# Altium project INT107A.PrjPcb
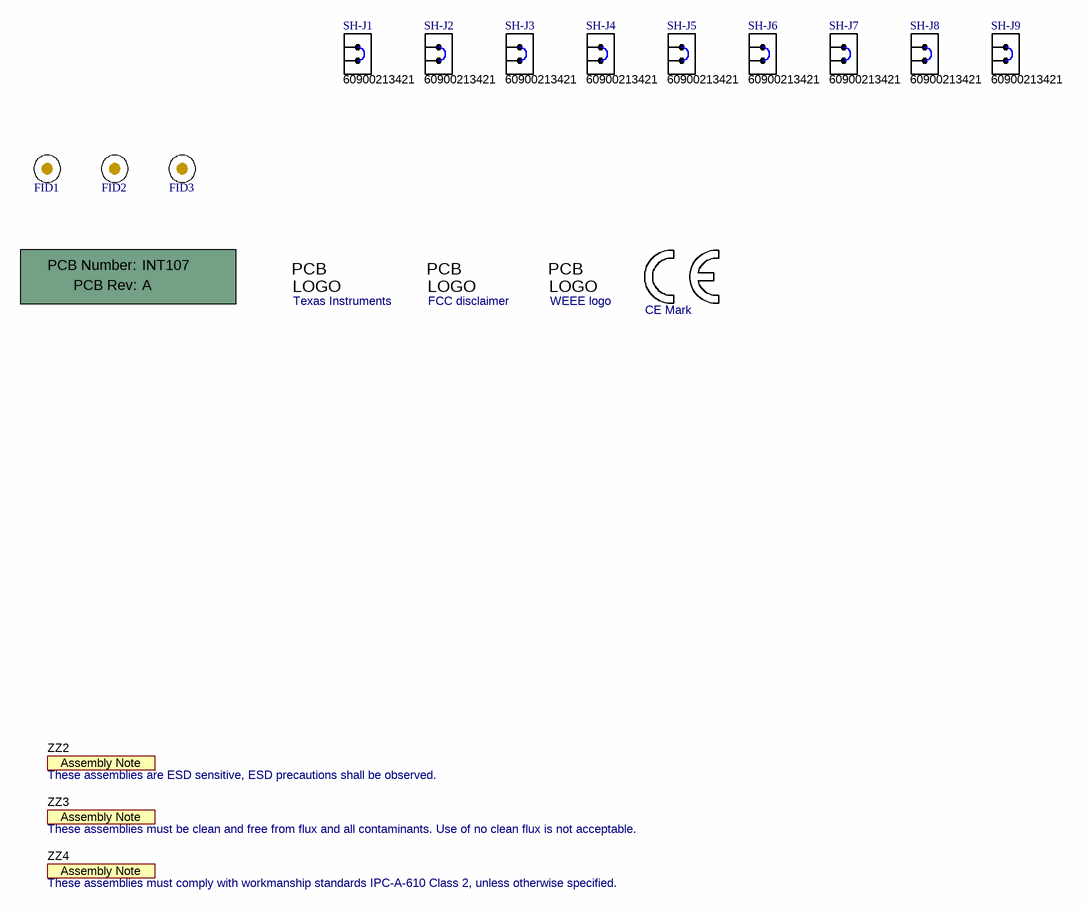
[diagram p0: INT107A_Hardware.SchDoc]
CopyrightYear: 2019; EVM_Orderable: BOOSTXL-CANFD-LIN; Orderable: BOOSTXL-CANFD-LIN; PCB_Layout: Jonathan Nerger; PCB_Rev: A; PRJ_Customer: Public Release; PRJ_Engineer: Jonathan Nerger; PRJ_Number: INT107; PRJ_Title: SPI to CAN FD SBC + LIN BoosterPack; SCH_Rev: A; TechSupport: http://www.ti.com/support; TID: N/A
2 sheets, 161 parts. Net scope: global (net labels, ports and power ports of the same name join across sheets).
Board file: INT107A_PCB.PcbDoc
Sheets:
  INT107A_Hardware.SchDoc
  INT107A_Schematic.SchDoc

## Sheet INT107A_Hardware.SchDoc: BOOSTXL-CANFD-LIN Hardwdare
size 431 x 279 mm; Date: Not shown in title block; ApprovedBy: Not shown in title block; CheckedBy: Not shown in title block; Author: Not shown in title block; CompanyName: Texas Instruments; DrawnBy: Jonathan Nerger; Engineer: Jonathan Nerger; Organization: Texas Instruments; Address1: Not shown in title block; Address2: Not shown in title block; Address3: Not shown in title block; Address4: Not shown in title block; DocumentNumber: 2; Revision: Use project parameter SCH_Rev; SheetNumber: 2; SheetTotal: 2; PageSetup: Record=PageOptions¦CenterHorizontal=True¦CenterVertical=True¦PrintScale=1.00¦XCorrection=1.00¦YCorrection=1.00¦PrintKind=0¦BorderSize=5000000¦LeftOffset=0¦BottomOffset=0¦Orientation=2¦PaperLength=1000¦PaperWidth=1000¦Scale=100¦PaperSource=15¦PrintQuality=600¦MediaType=1¦DitherType=10¦PaperKind=Letter¦PrintScaleMode=1

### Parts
!PCB1  Printed Circuit Board  (value not drawn)  (mechanical)
FID1  Fiducial  [Fiducial10-20]  (value not drawn)
FID2  Fiducial  [Fiducial10-20]  (value not drawn)
FID3  Fiducial  [Fiducial10-20]  (value not drawn)
Logo1  Texas Instruments  [TI_Stacked_Overlay_Small]  (no BOM)
Logo3  FCC disclaimer  [FCC_disclaimer]  (no BOM)
LOGO4  CE Mark  [CE_Mark_5mm]  (no BOM)
Logo5  WEEE logo  [WEEE_Minimum]  (no BOM)
SH-J1  60900213421  [Wurth_60900213421]
SH-J2  60900213421  [Wurth_60900213421]
SH-J3  60900213421  [Wurth_60900213421]
SH-J4  60900213421  [Wurth_60900213421]
SH-J5  60900213421  [Wurth_60900213421]
SH-J6  60900213421  [Wurth_60900213421]
SH-J7  60900213421  [Wurth_60900213421]
SH-J8  60900213421  [Wurth_60900213421]
SH-J9  60900213421  [Wurth_60900213421]
ZZ2  These assemblies are ESD sensitive, ESD precautions shall be observed.  [AssemblyNote]  (no BOM)
ZZ3  These assemblies must be clean and free from flux and all contaminants. Use of no clean flux is not acceptable.  [AssemblyNote]  (no BOM)
ZZ4  These assemblies must comply with workmanship standards IPC-A-610 Class 2, unless otherwise specified.  [AssemblyNote]  (no BOM)

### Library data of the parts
!PCB1 = CMP-0003618-2: Manufacturer: Any; PartNumber: INT107
FID1-FID3 = CMP-0077181-1: Fiducial mark.  There is nothing to buy or mount.
Logo1 = CMP-0074838-1: Texas Instrument Corporate Signature; SymbolCreator: a0412235; Lib Reference: TI_Logo
Logo3 = CMP-0074847-1: FCC_disclaimer
LOGO4 = CMP-0074844-1: SymbolCreator: a0412235
Logo5 = CMP-0074769-1
SH-J1-SH-J9 = CMP-0003761-2: Shunt, 2.54mm, Gold, Black; Manufacturer: Wurth Elektronik
ZZ2 = CMP-0077236-1
ZZ3 = CMP-0077237-1
ZZ4 = CMP-0077238-1

## Sheet INT107A_Schematic.SchDoc: BOOSTXL-CANFD-LIN Schematic
size 431 x 279 mm; Date: Not shown in title block; ApprovedBy: Not shown in title block; CheckedBy: Not shown in title block; Author: Not shown in title block; CompanyName: Texas Instruments; DrawnBy: Jonathan Nerger; Engineer: Jonathan Nerger; Organization: Texas Instruments; Address1: Not shown in title block; Address2: Not shown in title block; Address3: Not shown in title block; Address4: Not shown in title block; DocumentNumber: 1; Revision: Use project parameter SCH_Rev; SheetNumber: 1; SheetTotal: 2; PageSetup: Record=PageOptions¦CenterHorizontal=True¦CenterVertical=True¦PrintScale=1.00¦XCorrection=1.00¦YCorrection=1.00¦PrintKind=0¦BorderSize=5000000¦LeftOffset=0¦BottomOffset=0¦Orientation=2¦PaperLength=1000¦PaperWidth=1000¦Scale=100¦PaperSource=15¦PrintQuality=600¦MediaType=1¦DitherType=10¦PaperKind=Letter¦PrintScaleMode=1
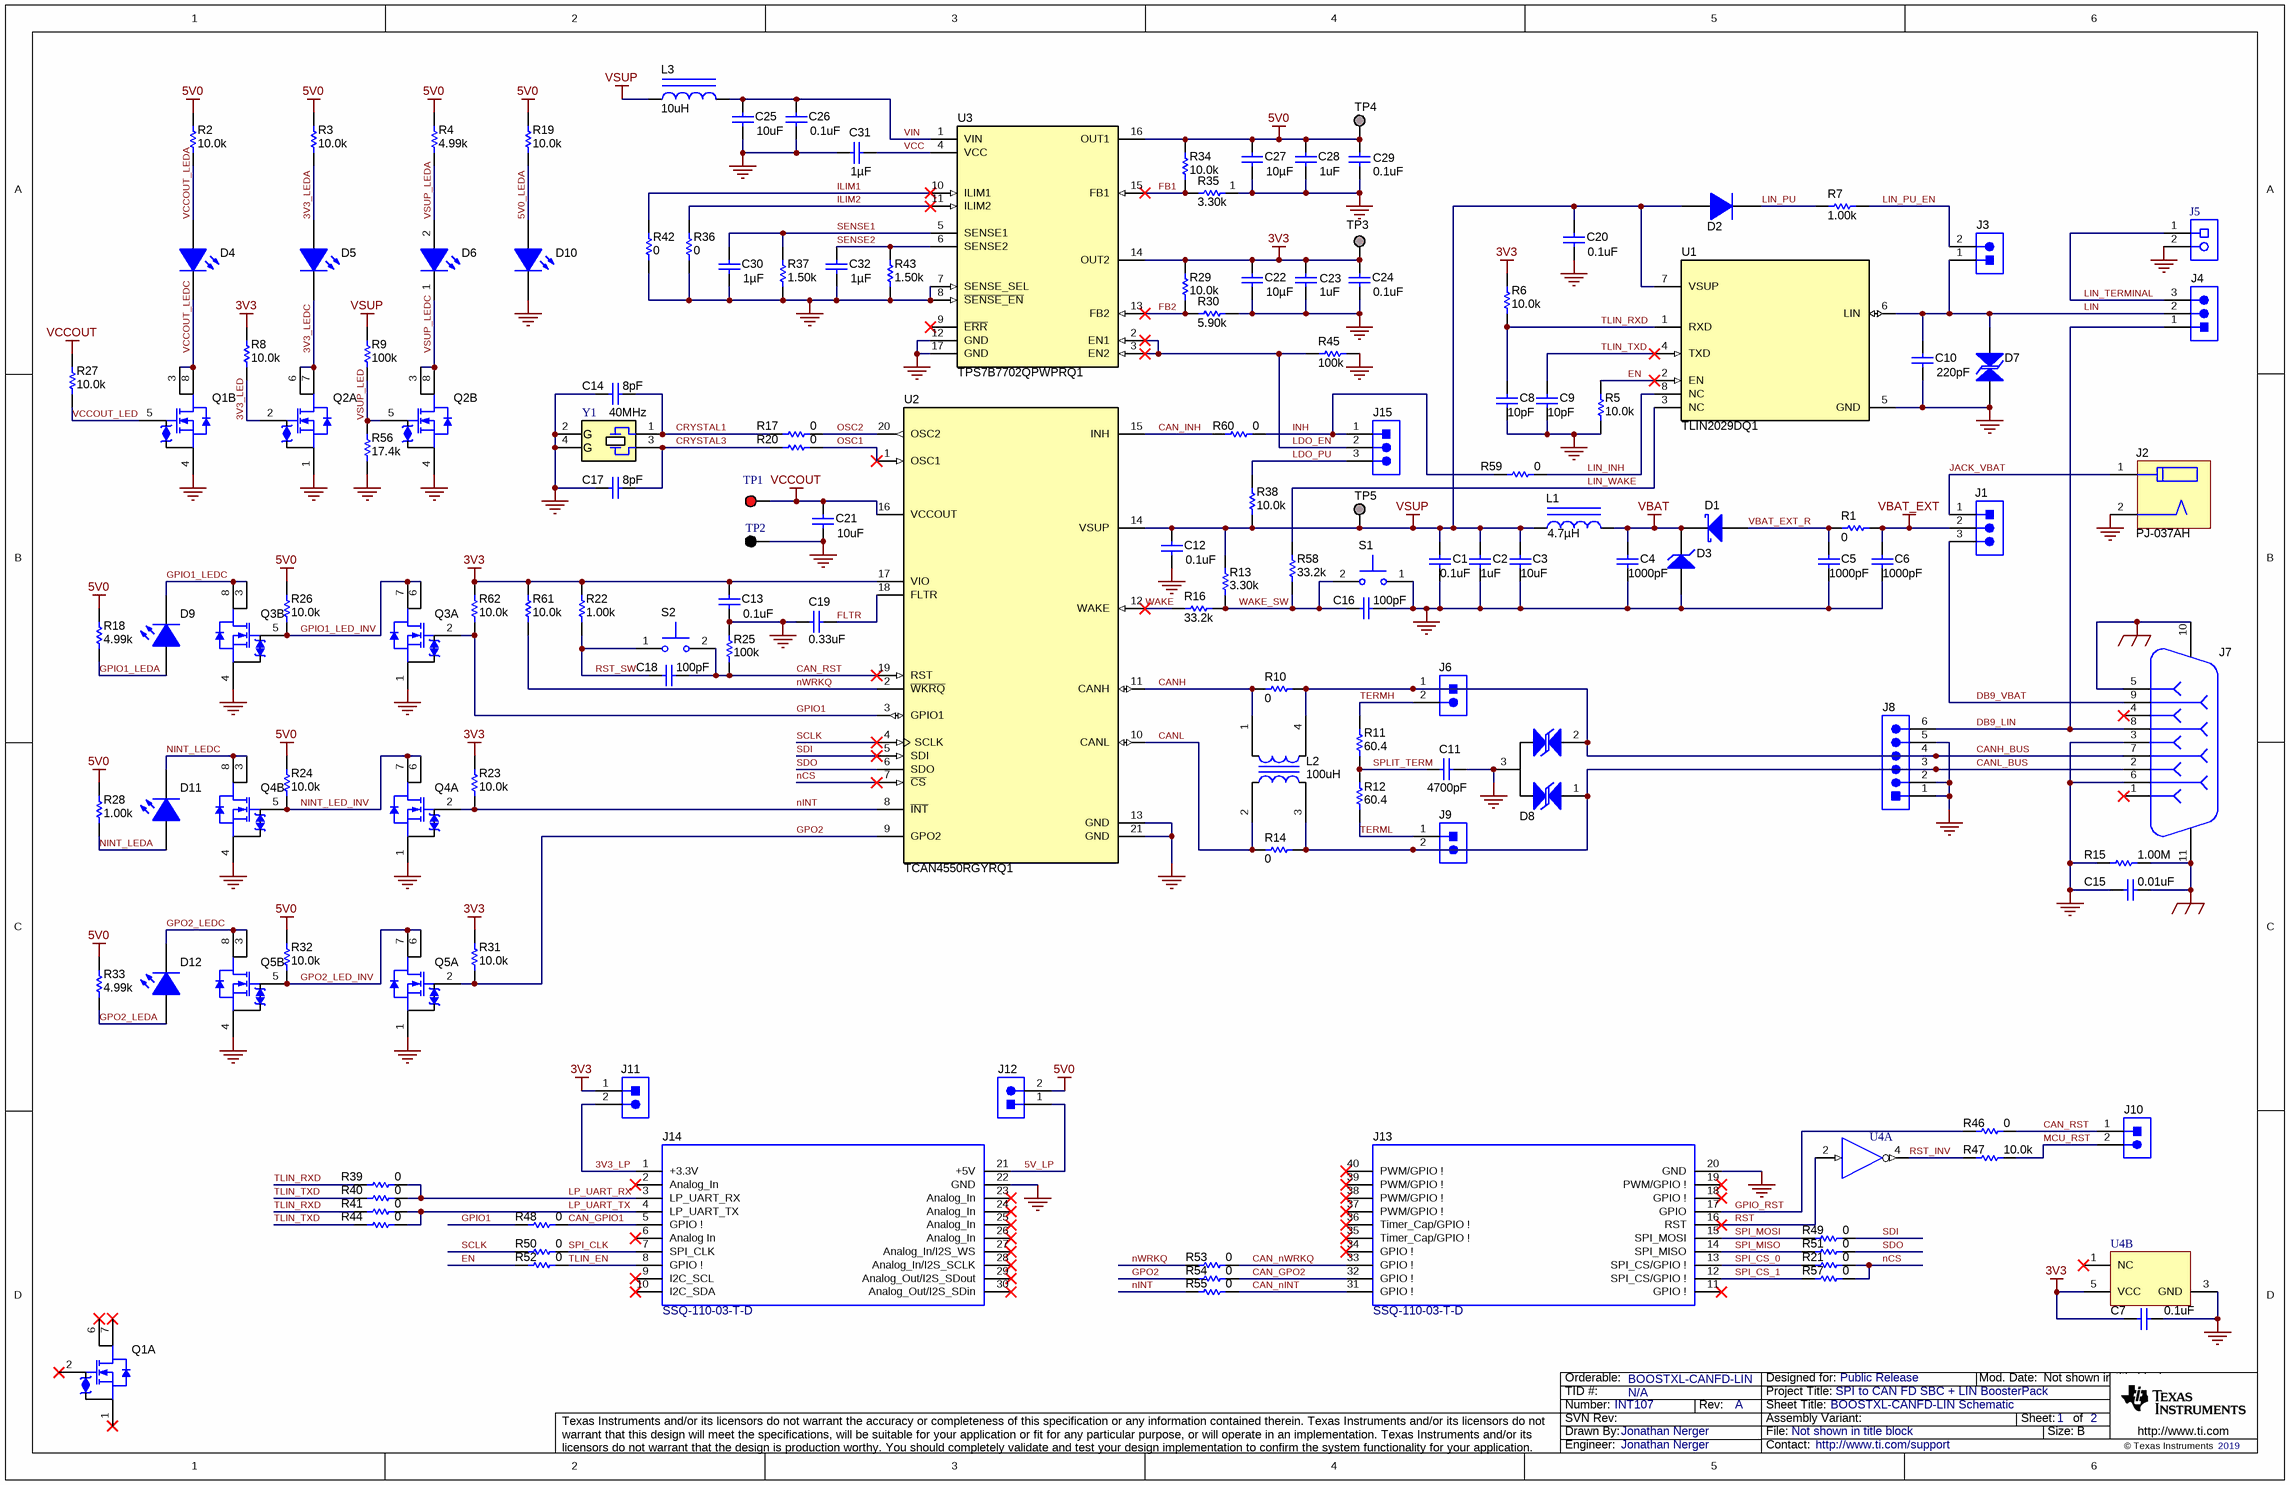
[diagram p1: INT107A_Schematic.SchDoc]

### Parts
C1  ValueDisplayed: 0.1uF  [0603S]  (hidden comment: CGA3E2X7R1H104K080AA)
C2  ValueDisplayed: 1uF  [0603S]  (hidden comment: UMK107AB7105KA-T)
C3  ValueDisplayed: 10uF  [1206_180]  (hidden comment: CL31B106KBHNNNE)
C4  ValueDisplayed: 1000pF  [0603S]  (hidden comment: CGA3E2X7R2A102K080AA)
C5  ValueDisplayed: 1000pF  [0603S]  (hidden comment: CGA3E2X7R2A102K080AA)
C6  ValueDisplayed: 1000pF  [0603S]  (hidden comment: CGA3E2X7R2A102K080AA)
C7  ValueDisplayed: 0.1uF  [0603S]  (hidden comment: CGA3E2X7R1H104K080AA)
C8  ValueDisplayed: 10pF  [0603S]  (hidden comment: CGA3E2NP01H100D080AA)
C9  ValueDisplayed: 10pF  [0603S]  (hidden comment: CGA3E2NP01H100D080AA)
C10  ValueDisplayed: 220pF  [0603S]  (hidden comment: 06035A221FAT2A)
C11  ValueDisplayed: 4700pF  [0603]  (hidden comment: 06031C472KAT2A)
C12  ValueDisplayed: 0.1uF  [0603S]  (hidden comment: CGA3E2X7R1H104K080AA)
C13  ValueDisplayed: 0.1uF  [0603S]  (hidden comment: CGA3E2X7R1H104K080AA)
C14  ValueDisplayed: 8pF  [0402S]  (hidden comment: CC0402DRNPO9BN8R0)
C15  ValueDisplayed: 0.01uF  [1206]  (hidden comment: 12061C103JAT2A)
C16  ValueDisplayed: 100pF  [0603S]  (hidden comment: 06035A101JAT2A)
C17  ValueDisplayed: 8pF  [0402S]  (hidden comment: CC0402DRNPO9BN8R0)
C18  ValueDisplayed: 100pF  [0603S]  (hidden comment: 06035A101JAT2A)
C19  ValueDisplayed: 0.33uF  [0603S]  (hidden comment: C0603C334K4RACTU)
C20  ValueDisplayed: 0.1uF  [0603S]  (hidden comment: CGA3E2X7R1H104K080AA)
C21  ValueDisplayed: 10uF  [0805]  (hidden comment: CL21B106KOQNNNE)
C22  ValueDisplayed: 10µF  [1206_180]  (hidden comment: C1206C106K4RACTU)
C23  ValueDisplayed: 1uF  [0603S]  (hidden comment: UMK107AB7105KA-T)
C24  ValueDisplayed: 0.1uF  [0603S]  (hidden comment: CGA3E2X7R1H104K080AA)
C25  ValueDisplayed: 10uF  [1206_180]  (hidden comment: CL31B106KBHNNNE)
C26  ValueDisplayed: 0.1uF  [0603S]  (hidden comment: CGA3E2X7R1H104K080AA)
C27  ValueDisplayed: 10µF  [1206_180]  (hidden comment: C1206C106K4RACTU)
C28  ValueDisplayed: 1uF  [0603S]  (hidden comment: UMK107AB7105KA-T)
C29  ValueDisplayed: 0.1uF  [0603S]  (hidden comment: CGA3E2X7R1H104K080AA)
C30  ValueDisplayed: 1µF  [0603S]  (hidden comment: GCM188R71C105KA64J)
C31  ValueDisplayed: 1µF  [0603S]  (hidden comment: GCM188R71C105KA64J)
C32  ValueDisplayed: 1µF  [0603S]  (hidden comment: GCM188R71C105KA64J)
D1  MBRA140T3G  [SMA]  (value not drawn)
D2  1N4148W-TP  [SOD-123]  (value not drawn)
D3  3SMAJ5936B-TP  [SMA]  (value not drawn)
D4  150060GS75000  [WL-SMCW_GREEN]  (value not drawn)
D5  150060GS75000  [WL-SMCW_GREEN]  (value not drawn)
D6  150060GS75000  [WL-SMCW_GREEN]  (value not drawn)
D7  PESD1LIN,115  [SOD-323-Bi]  (value not drawn)
D8  PESD1CAN,215  [SOT-23]  (value not drawn)
D9  150060YS75000  [WL-SMCW_YELLOW]  (value not drawn)
D10  150060GS75000  [WL-SMCW_GREEN]  (value not drawn)
D11  150060BS75000  [WL-SMCW_Blue]  (value not drawn)
D12  150060RS75000  [WL-SMCW_RED]  (value not drawn)
J1  TSW-103-07-G-S  [TSW-103-07-G-S]  (value not drawn)
J2  PJ-037AH  [CUI_PJ-037AH]
J3  TSW-102-07-G-S  [TSW-102-07-G-S]  (value not drawn)
J4  TSW-103-07-G-S  [TSW-103-07-G-S]  (value not drawn)
J5  OSTVN02A150  [On-Shore_OSTVN02A150]  (value not drawn)
J6  TSW-102-07-G-S  [TSW-102-07-G-S]  (value not drawn)
J7  5747840-5  [TE_5747840-5]  (value not drawn)
J8  TSW-106-07-G-S  [TSW-106-07-G-S]  (value not drawn)
J9  TSW-102-07-G-S  [TSW-102-07-G-S]  (value not drawn)
J10  TSW-102-07-G-S  [TSW-102-07-G-S]  (value not drawn)
J11  TSW-102-07-G-S  [TSW-102-07-G-S]  (value not drawn)
J12  TSW-102-07-G-S  [TSW-102-07-G-S]  (value not drawn)
J13  SSQ-110-03-T-D  [BoosterPack_40pin_J2J4]
J14  SSQ-110-03-T-D  [BoosterPack_40pin_J1J3]
J15  TSW-103-07-G-S  [TSW-103-07-G-S]  (value not drawn)
L1  ValueDisplayed: 4.7µH  [B82462A4]  (hidden comment: B82462A4472M000)
L2  ValueDisplayed: 100uH  [ACT45B]  (hidden comment: ACT45B-101-2P-TL003)
L3  ValueDisplayed: 10uH  [WE-TPC_2828]  (hidden comment: 744025100)
Q1  CSD85301Q2  [DQK0006B]  (value not drawn)  (parts A,B of 2)
Q2  CSD85301Q2  [DQK0006B]  (value not drawn)  (parts A,B of 2)
Q3  CSD85301Q2  [DQK0006B]  (value not drawn)  (parts A,B of 2)
Q4  CSD85301Q2  [DQK0006B]  (value not drawn)  (parts A,B of 2)
Q5  CSD85301Q2  [DQK0006B]  (value not drawn)  (parts A,B of 2)
R1  ValueDisplayed: 0  [5106]  (hidden comment: 5106)
R2  ValueDisplayed: 10.0k  [0402S]  (hidden comment: RC0402FR-0710KL)
R3  ValueDisplayed: 10.0k  [0402S]  (hidden comment: RC0402FR-0710KL)
R4  ValueDisplayed: 4.99k  [0402S]  (hidden comment: RC0402FR-074K99L)
R5  ValueDisplayed: 10.0k  [0402S]  (hidden comment: RC0402FR-0710KL)
R6  ValueDisplayed: 10.0k  [0402S]  (hidden comment: RC0402FR-0710KL)
R7  ValueDisplayed: 1.00k  [0402S]  (hidden comment: CRCW04021K00FKED)
R8  ValueDisplayed: 10.0k  [0402S]  (hidden comment: RC0402FR-0710KL)
R9  ValueDisplayed: 100k  [0402S]  (hidden comment: RC1005F104CS)
R10  ValueDisplayed: 0  [1206]  (hidden comment: ERJ-8GEY0R00V)
R11  ValueDisplayed: 60.4  [0603]  (hidden comment: RC0603FR-0760R4L)
R12  ValueDisplayed: 60.4  [0603]  (hidden comment: RC0603FR-0760R4L)
R13  ValueDisplayed: 3.30k  [0402S]  (hidden comment: ERJ-2RKF3301X)
R14  ValueDisplayed: 0  [1206]  (hidden comment: ERJ-8GEY0R00V)
R15  ValueDisplayed: 1.00M  [0402S]  (hidden comment: ERJ-2RKF1004X)
R16  ValueDisplayed: 33.2k  [0402S]  (hidden comment: CRCW040233K2FKED)
R17  ValueDisplayed: 0  [0402S]  (hidden comment: RC0402JR-070RL)
R18  ValueDisplayed: 4.99k  [0402S]  (hidden comment: RC0402FR-074K99L)
R19  ValueDisplayed: 10.0k  [0402S]  (hidden comment: RC0402FR-0710KL)
R20  ValueDisplayed: 0  [0402S]  (hidden comment: RC0402JR-070RL)
R21  ValueDisplayed: 0  [0402S]  (hidden comment: RC0402JR-070RL)
R22  ValueDisplayed: 1.00k  [0402S]  (hidden comment: RC0402FR-071KL)
R23  ValueDisplayed: 10.0k  [0402S]  (hidden comment: RC0402FR-0710KL)
R24  ValueDisplayed: 10.0k  [0402S]  (hidden comment: RC0402FR-0710KL)
R25  ValueDisplayed: 100k  [0402S]  (hidden comment: RC1005F104CS)
R26  ValueDisplayed: 10.0k  [0402S]  (hidden comment: RC0402FR-0710KL)
R27  ValueDisplayed: 10.0k  [0402S]  (hidden comment: RC0402FR-0710KL)
R28  ValueDisplayed: 1.00k  [0402S]  (hidden comment: RC0402FR-071KL)
R29  ValueDisplayed: 10.0k  [0402S]  (hidden comment: RC0402FR-0710KL)
R30  ValueDisplayed: 5.90k  [0402S]  (hidden comment: CRCW04025K90FKED)
R31  ValueDisplayed: 10.0k  [0402S]  (hidden comment: RC0402FR-0710KL)
R32  ValueDisplayed: 10.0k  [0402S]  (hidden comment: RC0402FR-0710KL)
R33  ValueDisplayed: 4.99k  [0402S]  (hidden comment: RC0402FR-074K99L)
R34  ValueDisplayed: 10.0k  [0402S]  (hidden comment: RC0402FR-0710KL)
R35  ValueDisplayed: 3.30k  [0402S]  (hidden comment: ERJ-2RKF3301X)
R36  ValueDisplayed: 0  [0402S]  (hidden comment: RC0402JR-070RL)
R37  ValueDisplayed: 1.50k  [0402S]  (hidden comment: CRCW04021K50FKED)
R38  ValueDisplayed: 10.0k  [0402S]  (hidden comment: RC0402FR-0710KL)
R39  ValueDisplayed: 0  [0402S]  (hidden comment: RC0402JR-070RL)
R40  ValueDisplayed: 0  [0402S]  (hidden comment: RC0402JR-070RL)
R41  ValueDisplayed: 0  [0402S]  (hidden comment: RC0402JR-070RL)
R42  ValueDisplayed: 0  [0402S]  (hidden comment: RC0402JR-070RL)
R43  ValueDisplayed: 1.50k  [0402S]  (hidden comment: CRCW04021K50FKED)
R44  ValueDisplayed: 0  [0402S]  (hidden comment: RC0402JR-070RL)
R45  ValueDisplayed: 100k  [0402S]  (hidden comment: RC1005F104CS)
R46  ValueDisplayed: 0  [0402S]  (hidden comment: RC0402JR-070RL)
R47  ValueDisplayed: 10.0k  [0402S]  (hidden comment: RC0402FR-0710KL)
R48  ValueDisplayed: 0  [0402S]  (hidden comment: RC0402JR-070RL)
R49  ValueDisplayed: 0  [0402S]  (hidden comment: RC0402JR-070RL)
R50  ValueDisplayed: 0  [0402S]  (hidden comment: RC0402JR-070RL)
R51  ValueDisplayed: 0  [0402S]  (hidden comment: RC0402JR-070RL)
R52  ValueDisplayed: 0  [0402S]  (hidden comment: RC0402JR-070RL)
R53  ValueDisplayed: 0  [0402S]  (hidden comment: RC0402JR-070RL)
R54  ValueDisplayed: 0  [0402S]  (hidden comment: RC0402JR-070RL)
R55  ValueDisplayed: 0  [0402S]  (hidden comment: RC0402JR-070RL)
R56  ValueDisplayed: 17.4k  [0402S]  (hidden comment: CRCW040217K4FKED)
R57  ValueDisplayed: 0  [0402S]  (hidden comment: RC0402JR-070RL)
R58  ValueDisplayed: 33.2k  [0402S]  (hidden comment: CRCW040233K2FKED)
R59  ValueDisplayed: 0  [0402S]  (hidden comment: RC0402JR-070RL)
R60  ValueDisplayed: 0  [0402S]  (hidden comment: RC0402JR-070RL)
R61  ValueDisplayed: 10.0k  [0402S]  (hidden comment: RC0402FR-0710KL)
R62  ValueDisplayed: 10.0k  [0402S]  (hidden comment: RC0402FR-0710KL)
S1  B3U-1000P  [SW_B3U-1000P]  (value not drawn)
S2  B3U-1000P  [SW_B3U-1000P]  (value not drawn)
TP1  5010  [Keystone5010]  (value not drawn)
TP2  5011  [Keystone5011]  (value not drawn)
TP3  TP_SM_1MM  [TP_SM_1MM]  (value not drawn)  (no BOM)
TP4  TP_SM_1MM  [TP_SM_1MM]  (value not drawn)  (no BOM)
TP5  TP_SM_1MM  [TP_SM_1MM]  (value not drawn)  (no BOM)
U1  TLIN2029DQ1  [D0008A_N]
U2  TCAN4550RGYRQ1  [RGY0020C]
U3  TPS7B7702QPWPRQ1  [PWP0016J_N]
U4  SN74AUP1T04DCKR  [DCK0005A_N]  (value not drawn)  (parts A,B of 2)
Y1  Frequency_Fixed: 40MHz  [XTAL_NX2016SA]  (hidden comment: NX2016SA-40M-STD-CZS-3)

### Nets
3V3: C7.1 C13.1 C22.2 C23.1 C24.1 J11.1 R6.2 R8.2 R22.2 R23.2 R29.2 R31.2 R61.2 R62.2 TP3.1 U2.17(VIO) U3.14(OUT2) U4.5(VCC)
5V0: C27.2 C28.1 C29.1 J12.2 R2.2 R3.2 R4.2 R18.2 R19.2 R24.2 R26.2 R28.2 R32.2 R33.2 R34.1 TP4.1 U3.16(OUT1)
GND: C1.2 C2.2 C3.2 C4.2 C5.2 C6.2 C7.2 C8.2 C9.2 C10.2 C11.1 C12.2 C13.2 C14.2 C15.2 C16.2 C17.2 C19.2 C20.2 C21.2 C22.1 C23.2 C24.2 C25.2 C26.2 C27.1 C28.2 C29.2 C30.2 C31.2 C32.2 D3.2(A) D7.1 D8.3 D10.1(K) J2.2 J5.2 J7.3 J7.6 J8.1 J8.2 J8.5 J13.20(GND) J14.22(GND) Q1.4(S2) Q2.1(S1) Q2.4(S2) Q3.1(S1) Q3.4(S2) Q4.1(S1) Q4.4(S2) Q5.1(S1) Q5.4(S2) R5.1 R15.1 R25.1 R30.2 R35.1 R36.2 R37.1 R42.2 R43.1 R45.2 R56.1 S1.1 TP2.1 U1.5(GND) U2.13(GND) U2.21(GND) U3.7(SENSE_SEL) U3.8(~{SENSE_EN}) U3.12(GND) U3.17(GND) U4.3(GND) Y1.2(GND) Y1.4(GND)
SHIELD_GND: C15.1 J7.5 J7.10 J7.11 R15.2
VBAT: C4.1 D1.1(K) D3.1(K) L1.2
VBAT_EXT: C6.1 J1.2 R1.2
VCCOUT: C21.1 R27.2 TP1.1 U2.16(VCCOUT)
VSUP: C1.1 C2.1 C3.1 C12.1 C20.1 D2.2(A) L1.1 L3.1 R9.1 R13.2 R38.1 TP5.1 U1.7(VSUP) U2.14(VSUP)
3V3_LED: Q2.2(G1) R8.1
3V3_LEDA: D5.2(A) R3.1
3V3_LEDC: D5.1(K) Q2.6(D1) Q2.7(D1)
3V3_LP: J11.2 J14.1(+3.3V)
5V0_LEDA: D10.2(A) R19.1
5V_LP: J12.1 J14.21(+5V)
CAN_GPIO1: J14.5(GPIO_!) R48.2
CAN_GPO2: J13.32(GPIO_!) R54.2
CAN_INH: R60.2 U2.15(INH)
CAN_nINT: J13.31(GPIO_!) R55.2
CAN_nWRKQ: J13.33(GPIO_!) R53.2
CAN_RST: C18.1 J10.1 R25.2 R46.2 S2.2 U2.19(RST)
CANH: L2.1 R10.1 U2.11(CANH)
CANH_BUS: D8.2 J6.1 J7.7 J8.4 L2.4 R10.2
CANL: L2.2 R14.1 U2.10(CANL)
CANL_BUS: D8.1 J7.2 J8.3 J9.2 L2.3 R14.2
CRYSTAL1: C14.1 R17.2 Y1.1
CRYSTAL3: C17.1 R20.2 Y1.3
DB9_LIN: J4.1 J7.8 J8.6
DB9_VBAT: J1.3 J7.9
EN: R5.2 R52.1 U1.2(EN)
FB1: R34.2 R35.2 U3.15(FB1)
FB2: R29.1 R30.1 U3.13(FB2)
FLTR: C19.1 U2.18(FLTR)
GPIO1: Q3.2(G1) R48.1 R62.1 U2.3(GPIO1)
GPIO1_LED_INV: Q3.5(G2) Q3.6(D1) Q3.7(D1) R26.1
GPIO1_LEDA: D9.2(A) R18.1
GPIO1_LEDC: D9.1(K) Q3.3(D2) Q3.8(D2)
GPIO_RST: J13.17(GPIO) R46.1
GPO2: Q5.2(G1) R31.1 R54.1 U2.9(GPO2)
GPO2_LED_INV: Q5.5(G2) Q5.6(D1) Q5.7(D1) R32.1
GPO2_LEDA: D12.2(A) R33.1
GPO2_LEDC: D12.1(K) Q5.3(D2) Q5.8(D2)
ILIM1: R42.1 U3.10(ILIM1)
ILIM2: R36.1 U3.11(ILIM2)
INH: J15.1 R59.2 R60.1
JACK_VBAT: J1.1 J2.1
LDO_EN: J15.2 R45.1 U3.2(EN1) U3.3(EN2)
LDO_PU: J15.3 R38.2
LIN: C10.1 D7.2 J3.1 J4.2 U1.6(LIN)
LIN_INH: R59.1 U1.8(NC)
LIN_PU: D2.1(K) R7.2
LIN_PU_EN: J3.2 R7.1
LIN_TERMINAL: J4.3 J5.1
LIN_WAKE: R58.1 U1.3(NC)
LP_UART_RX: J14.3(LP_UART_RX) R39.1 R40.1
LP_UART_TX: J14.4(LP_UART_TX) R41.1 R44.1
MCU_RST: J10.2 R47.1
nCS: R21.2 R57.2 U2.7(~{CS})
nINT: Q4.2(G1) R23.1 R55.1 U2.8(~{INT})
NINT_LED_INV: Q4.5(G2) Q4.6(D1) Q4.7(D1) R24.1
NINT_LEDA: D11.2(A) R28.1
NINT_LEDC: D11.1(K) Q4.3(D2) Q4.8(D2)
nWRKQ: R53.1 R61.1 U2.2(~{WKRQ})
OSC1: R20.1 U2.1(OSC1)
OSC2: R17.1 U2.20(OSC2)
RST: J13.16(RST) U4.2(A)
RST_INV: R47.2 U4.4(Y)
RST_SW: C18.2 R22.1 S2.1
SCLK: R50.1 U2.4(SCLK)
SDI: R49.2 U2.5(SDI)
SDO: R51.2 U2.6(SDO)
SENSE1: C30.1 R37.2 U3.5(SENSE1)
SENSE2: C32.1 R43.2 U3.6(SENSE2)
SPI_CLK: J14.7(SPI_CLK) R50.2
SPI_CS_0: J13.13(SPI_CS/GPIO_!) R21.1
SPI_CS_1: J13.12(SPI_CS/GPIO_!) R57.1
SPI_MISO: J13.14(SPI_MISO) R51.1
SPI_MOSI: J13.15(SPI_MOSI) R49.1
SPLIT_TERM: C11.2 R11.1 R12.2
TERMH: J6.2 R11.2
TERML: J9.1 R12.1
TLIN_EN: J14.8(GPIO_!) R52.2
TLIN_RXD: C8.1 R6.1 R39.2 R41.2 U1.1(RXD)
TLIN_TXD: C9.1 R40.2 R44.2 U1.4(TXD)
VBAT_EXT_R: C5.1 D1.2(A) R1.1
VCC: C31.1 U3.4(VCC)
VCCOUT_LED: Q1.5(G2) R27.1
VCCOUT_LEDA: D4.2(A) R2.1
VCCOUT_LEDC: D4.1(K) Q1.3(D2) Q1.8(D2)
VIN: C25.1 C26.1 L3.2 U3.1(VIN)
VSUP_LED: Q2.5(G2) R9.2 R56.2
VSUP_LEDA: D6.2(A) R4.1
VSUP_LEDC: D6.1(K) Q2.3(D2) Q2.8(D2)
WAKE: R16.2 U2.12(WAKE)
WAKE_SW: C16.1 R13.1 R16.1 R58.2 S1.2

Not connected (* = marked no-connect by the designer): J7 1* 4*; J13 11(GPIO_!)* 18(GPIO_!)* 19(PWM/GPIO_!)* 34(GPIO_!)* 35(Timer_Cap/GPIO_!)* 36(Timer_Cap/GPIO_!)* 37(PWM/GPIO_!)* 38(PWM/GPIO_!)* 39(PWM/GPIO_!)* 40(PWM/GPIO_!)*; J14 2(Analog_In)* 6(Analog_In)* 9(I2C_SCL)* 10(I2C_SDA)* 23(Analog_In)* 24(Analog_In)* 25(Analog_In)* 26(Analog_In)* 27(Analog_In/I2S_WS)* 28(Analog_In/I2S_SCLK)* 29(Analog_Out/I2S_SDout)* 30(Analog_Out/I2S_SDin)*; Q1 1(S1)* 2(G1)* 6(D1)* 7(D1)*; U3 9(~{ERR})*; U4 1(NC)*

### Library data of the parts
C1 C7 C12 C13 C20 C24 C26 C29 = CMP-0007078-4: CAP, CERM, 0.1 uF, 50 V, +/- 10%, X7R, AEC-Q200 Grade 1, 0603; Manufacturer: TDK; TaMin_C: -55°C; ESR_ohm: 0.0296; Polarized: N; SizeAreaWB_mm2: 4.68; Value1: 0.0296 ohm; U/M: EA; Value: 0.1uF; TaMax_C: 125°C; SizeZ_mm: 1; SizeX_mm: 1.6; SizeY_mm: 0.8; Cap_Case: 0603; Value2: 50V; SizeArea_mm2: 1.28; AEC Qualified: Y; Cap_F: 100nF; IRMS_A: 971.99mA; AEC Category: Q200
C2 C23 C28 = CMP-0007508-5: CAP, CERM, 1 uF, 50 V, +/- 10%, X7R, 0603; Manufacturer: Taiyo Yuden; TaMin_C: -55°C; Polarized: N; SizeAreaWB_mm2: 4.68; Value1: Unknown; U/M: EA; Value: 1uF; TaMax_C: 125°C; SizeZ_mm: 1; SizeX_mm: 1.6; SizeY_mm: 0.8; Cap_Case: 0603; Value2: 50V; SizeArea_mm2: 1.28; Cap_F: 1µF; AEC Category: Q200
C3 C25 = CMP-0008802-2: CAP, CERM, 10 uF, 50 V, +/- 10%, X7R, 1206; Manufacturer: Samsung; TaMin_C: -55°C; Polarized: N; SizeAreaWB_mm2: 10.92; Value1: Unknown; U/M: EA; Value: 10uF; TaMax_C: 125°C; SizeZ_mm: 1.8; SizeX_mm: 3.2; SizeY_mm: 1.6; Cap_Case: 1206; Value2: 50V; SizeArea_mm2: 5.12; Cap_F: 10µF; AEC Category: Q200
C4-C6 = CMP-0007081-4: CAP, CERM, 1000 pF, 100 V, +/- 10%, X7R, AEC-Q200 Grade 1, 0603; Manufacturer: TDK; TaMin_C: -55°C; Polarized: N; SizeAreaWB_mm2: 4.68; Value1: 1.97137 ohm; U/M: EA; Value: 1000pF; TaMax_C: 125°C; SizeZ_mm: 1; SizeX_mm: 1.6; SizeY_mm: 0.8; Cap_Case: 0603; Value2: 100V; SizeArea_mm2: 1.28; AEC Qualified: Y; Cap_F: 1nF; AEC Category: Q200; ESR_ohm: 1.97137; IRMS_A: 305.705mA
C8 C9 = CMP-0007074-4: CAP, CERM, 10 pF, 50 V, +/- 5%, C0G/NP0, 0603; Manufacturer: TDK; TaMin_C: -55°C; Polarized: N; SizeAreaWB_mm2: 4.68; Value1: Unknown; U/M: EA; Value: 10pF; TaMax_C: 150°C; SizeZ_mm: 1; SizeX_mm: 1.6; SizeY_mm: 0.8; Cap_Case: 0603; Value2: 50V; SizeArea_mm2: 1.28; AEC Category: Q200
C10 = CMP-0006776-4: CAP, CERM, 220 pF, 50 V, +/- 1%, C0G/NP0, 0603; Manufacturer: AVX; TaMin_C: -55°C; ESR_ohm: 0.083; Polarized: N; SizeAreaWB_mm2: 4.68; Value1: 0.083 ohm; U/M: EA; Value: 220pF; TaMax_C: 125°C; SizeZ_mm: 1; SizeX_mm: 1.6; SizeY_mm: 0.8; Cap_Case: 0603; Value2: 50V; SizeArea_mm2: 1.28; AEC Category: Q200
C11 = CMP-0006746-5: CAP, CERM, 4700 pF, 100 V, +/- 10%, X7R, 0603; Manufacturer: AVX; TaMin_C: -55°C; ESR_ohm: 1.36d; Polarized: N; SizeAreaWB_mm2: 4.68; Value1: 0.136 ohm; U/M: EA; Value: 4700pF; TaMax_C: 125°C; SizeZ_mm: 1; SizeX_mm: 1.6; SizeY_mm: 0.8; Value2: 100V; SizeArea_mm2: 1.28; Cap_F: 4.7nF; AEC Category: Q200
C14 C17 = CMP-0860185-1: CAP, CERM, 8 pF, 50 V,+/- 6.25%, C0G/NP0, 0402; Manufacturer: Yageo; TaMin_C: -55°C; Polarized: N; SizeAreaWB_mm2: 3; U/M: EA; Value: 8pF; TaMax_C: 125°C; SizeZ_mm: 0.6; SizeX_mm: 1; SizeY_mm: 0.5; Cap_Case: 0402; Value2: 50V; AEC Category: Q200
C15 = CMP-0008484-2: CAP, CERM, 0.01 uF, 100 V, +/- 5%, X7R, 1206; Manufacturer: AVX; TaMin_C: -55°C; ESR_ohm: 1.19d; Polarized: N; SizeAreaWB_mm2: 10.92; Value1: 0.119 ohm; U/M: EA; Value: 0.01uF; TaMax_C: 125°C; SizeZ_mm: 1.35; SizeX_mm: 3.2; SizeY_mm: 1.6; Value2: 100V; SizeArea_mm2: 5.12; Cap_F: 10nF; AEC Category: Q200
C16 C18 = CMP-0006763-4: CAP, CERM, 100 pF, 50 V, +/- 5%, C0G/NP0, 0603; Manufacturer: AVX; TaMin_C: -55°C; ESR_ohm: 1.19d; Polarized: N; SizeAreaWB_mm2: 4.68; Value1: 0.119 ohm; U/M: EA; Value: 100pF; TaMax_C: 125°C; SizeZ_mm: 1; SizeX_mm: 1.6; SizeY_mm: 0.8; Cap_Case: 0603; Value2: 50V; SizeArea_mm2: 1.28; AEC Category: Q200
C19 = CMP-0006924-4: CAP, CERM, 0.33 uF, 16 V, +/- 10%, X7R, 0603; Manufacturer: Kemet; TaMin_C: -55°C; Polarized: N; SizeAreaWB_mm2: 4.68; Value1: Unknown; U/M: EA; Value: 0.33uF; TaMax_C: 125°C; SizeZ_mm: 1; SizeX_mm: 1.6; SizeY_mm: 0.8; Cap_Case: 0603; Value2: 16V; SizeArea_mm2: 1.28; Cap_F: 330nF; AEC Category: Q200
C21 = CMP-0007995-2: CAP, CERM, 10 uF, 16 V, +/- 10%, X7R, 0805; Manufacturer: Samsung Electro-Mechanics; TaMin_C: -55°C; Polarized: N; SizeAreaWB_mm2: 6.75; Value1: Unknown; U/M: EA; Value: 10uF; TaMax_C: 125°C; SizeZ_mm: 1.45; SizeX_mm: 2; SizeY_mm: 1.25; Value2: 16V; SizeArea_mm2: 2.5; Cap_F: 10µF; AEC Category: Q200
C22 C27 = CMP-0078542-1: CAP, CERM, 10 µF, 16 V,+/- 10%, X7R, 1206; Manufacturer: Kemet; SizeAreaWB_mm2: 10.92; SizeArea_mm2: 5.12; AEC Qualified: N; AEC Category: Q200; Value: 10uF; TaMax_C: 125°C; SizeZ_mm: 1.8; TaMin_C: -55°C; VDC_V: 16V; SizeY_mm: 1.6; U/M: EA; SizeX_mm: 3.2; Cap_Case: 1206
C30-C32 = CMP-0079154-1: CAP, CERM, 1 µF, 16 V,+/- 10%, X7R, AEC-Q200 Grade 1, 0603; Manufacturer: MuRata; SizeAreaWB_mm2: 4.68; SizeArea_mm2: 1.28; AEC Qualified: Y; AEC Category: Q200; Value: 1uF; TaMax_C: 125°C; SizeZ_mm: 1; Polarized: N; TaMin_C: -55°C; VDC_V: 16V; SizeY_mm: 0.8; U/M: EA; SizeX_mm: 1.6; Cap_Case: 0603
D1 = CMP-0028550-2: Diode, Schottky, 40 V, 1 A, SMA; Manufacturer: ON Semiconductor; Io_A: 1A; Green_Lifecycle: Not Set; SizeAreaWB_mm2: 37.3428; Vr_V: 40V; Green_REACh: Incomplete; TJmax_C: 125°C; Value: 40V; SizeZ_mm: 2.87; SizeX_mm: 5.59; SizeY_mm: 2.92; Vf_V: 550mV; Value2: 0.55V; SizeArea_mm2: 16.3228; AEC Category: Q101; RJC_CperW: 35
D2 = CMP-0076974-2: Diode, Switching, 100 V, 0.15 A, SOD-123; Manufacturer: Micro Commercial Components; SizeAreaWB_mm2: 13.095; Vr_V: 100V; SizeArea_mm2: 6.545; TJmax_C: 150°C; AEC Category: Q101; Value: 100V; SizeZ_mm: 1.35; Green_REACh: Incomplete; Io_A: 150mA; Vf_V: 1.25V; SizeY_mm: 1.7; Green_Lifecycle: Not Set; Value1: 0.15A; SizeX_mm: 3.85
D3 = CMP-0005515-4: Diode, Zener, 30 V, 3 W, SMA; Manufacturer: Micro Commercial Components; Power_W: 3W; SizeAreaWB_mm2: 37.3428; Vz_V: 30V; RJA_CperW: 226; Value: 30V; SizeZ_mm: 2.87; SizeX_mm: 5.59; SizeY_mm: 2.92; SizeArea_mm2: 16.3228; AEC Category: Q101
D4-D6 D10 = CMP-0002905-2: LED, Green, SMD; Manufacturer: Wurth Elektronik; Io_A: 20mA; Tjmax_C: 85°C; Value1: W; Angle: 140; Vf_V: 3.2V; Type: InGaN
D7 = CMP-0005821-3: Diode, TVS, Bi, 15 V, SOD-323; Manufacturer: NXP Semiconductor; SizeAreaWB_mm2: 8.695; Value1: 160W; Value: 15V; SizeZ_mm: 1; SizeX_mm: 2.7; SizeY_mm: 1.35; SizeArea_mm2: 3.645; AEC Category: Q101
D8 = CMP-0005920-3: Diode, TVS, Bi, 24 V, 70 Vc, AEC-Q101, SOT-23; Manufacturer: NXP Semiconductor; SizeAreaWB_mm2: 14; Value1: 200W; Value: 24V; SizeZ_mm: 1.1; SizeX_mm: 2.5; SizeY_mm: 3; SizeArea_mm2: 7.5; AEC Qualified: Y; AEC Category: Q101; Ipp: 3A; Vbr_Max: 30.3V; Vbr_Min: 25.4V; Vc: 70V
D9 = CMP-0002892-3: LED, Yellow, SMD; Manufacturer: Wurth Elektronik; Io_A: 20mA; Value1: W; Vf_V: 2V; Type: AlInGaP
D11 = CMP-0002946-3: LED, Blue, SMD; Manufacturer: Wurth Elektronik; Io_A: 30mA; Value1: 0.105W; Vf_V: 3.2V; Type: InGaN; Angle: 140; Power_TotalModule: 105mW; Tjmax_C: 85°C; Vr_V: 5V
D12 = CMP-0002947-3: LED, Red, SMD; Manufacturer: Wurth Elektronik; Io_A: 30mA; Power_TotalModule: 72mW; Vr_V: 5V; Tjmax_C: 85°C; Value1: 0.072W; Angle: 140; Vf_V: 2V; Type: AlInGaP
J1 J4 J15 = CMP-0075407-2: Header, 100mil, 3x1, Gold, TH; Manufacturer: Samtec; Pitch_mm: 2.54; Gender: Male; Cert_CSA: Y; Row_Count: 1; Cert_CULUS: N; Current_A: 6.3A; Green_Lifecycle: Active; Green_REACh: Passed; Voltage_V: 550V
J2 = CMP-0075114-1: Power Jack, 2mm, R/A, TH; Manufacturer: CUI Inc.; CNHeader: False; Shrouded: N; Gender: Male; Row_Count: 1; Pitch_mm: 6
J3 J6 J9-J12 = CMP-0075405-2: Header, 100mil, 2x1, Gold, TH; Manufacturer: Samtec; Pitch_mm: 2.54; Gender: Male; Cert_CSA: Y; Row_Count: 1; Cert_CULUS: N; Current_A: 6.3A; Green_Lifecycle: Active; Green_REACh: Passed; Voltage_V: 550V
J5 = CMP-0075076-1: Terminal Block, 2.54mm, 2x1, Brass, TH; Manufacturer: On-Shore Technology; CNHeader: False; Green_Lifecycle: Not Set; Green_REACh: Incomplete; CT: True
J7 = CMP-0054938-4: D-Sub, 2.74mm, 9 Position, R/A, TH; Manufacturer: TE Connectivity; CNHeader: FALSE; Gender: Male; Row_Count: 2; Pitch_mm: 2.74; ContactFinish: Gold; CT: TRUE; Cert_UL: Y
J8 = CMP-0075413-2: Header, 100mil, 6x1, Gold, TH; Manufacturer: Samtec; Pitch_mm: 2.54; Cert_VDE: N; Gender: Male; Cert_CSA: Y; Voltage_V: 550V; Green_REACh: Passed; Current_A: 6.3A; Green_Lifecycle: Active; Row_Count: 1
J13 = CMP-0078266-4: Receptacle, 2.54mm, 10x2, Tin, TH; Manufacturer: Samtec; Alternate Manufacturer: Major League Electronics; Alternate PartNumber: CRD-081413-A-G; Note: Booster Pack 40 pin J2 and J4; Green_Lifecycle: Active; Green_REACh: Incomplete
J14 = CMP-0003837-4: Receptacle, 2.54mm, 10x2, Tin, TH; Manufacturer: Samtec; Alternate Manufacturer: Major League Electronics; Alternate PartNumber: CRD-081413-A-G; Note: Booster Pack 40 pin J1 and J3; Green_Lifecycle: Active; Green_REACh: Incomplete
L1 = CMP-0001617-1: Inductor, Wirewound, Ferrite, 4.7 µH, 1.65 A, 0.08 ohm, AEC-Q200 Grade 0, SMD; Manufacturer: TDK; Isat: 2.8A @ 10% inductance drop; Irms: 1.65A @ 40C rise; SizeAreaWB_mm2: 64.0; DCR_ohm: 0.08; Value: 4.7uH; Imax_A: 1.65A; SizeZ_mm: 3.0; SizeX_mm: 6.0; SizeArea_mm2: 36.0; AEC Qualified: Y; AEC Grade: 0; AEC Category: Q200
L2 = CMP-0062430-2: Inductor, Ferrite, 100 uH, 0.15 A, 2 ohm, SMD; Manufacturer: TDK; Isat: 0.15A @ % inductance drop; Green_Lifecycle: Active; SizeAreaWB_mm2: 23.1; DCR_ohm: 2; Green_REACh: Passed; Value1: 2 ohm; Value: 100uH; Imax_A: 1.5dA; SizeZ_mm: 3; SizeX_mm: 4.5; SizeY_mm: 3.2; Value2: 0.15A; SizeArea_mm2: 14.4; Ind_H: 100µH; AEC Category: Q200
L3 = CMP-0063757-1: Inductor, Shielded Drum Core, Ferrite, 10 uH, 1 A, 0.17 ohm, SMD; Manufacturer: Wurth Elektronik; Isat: 1.1A @ 35% inductance drop; Irms: 1A @ 40C rise; Green_Lifecycle: Active; SizeAreaWB_mm2: 14.44; DCR_ohm: 1.7d; Green_REACh: Passed; Value: 10uH; Imax_A: 1A; SizeZ_mm: 3; SizeX_mm: 2.8; SizeArea_mm2: 7.84; Ind_H: 10µH; AEC Category: Q200
Q1-Q5 = CMP-0000208-1: MOSFET, 2-CH, N-CH, 20 V, 6.7 A, DQK0006B (WSON-6); Alternate Manufacturer: None; Manufacturer: Texas Instruments; SizeZ_mm: 0.8; ChType: N; Value2: 4.2 nC; Value1: 0.02; VdsMax_V: 20V; SizeX_mm: 2; Vgs_V: 10V; Value: 20V; Rdson45_ohm: 0.023; SizeArea_mm2: 4; AEC Category: Q101; IdsMax_A: 6.7A; SizeAreaWB_mm2: 9; U/M: EA; QgTyp_nC: 4.2
R1 = CMP-0020833-2: RES, 0, 1%, 0.5 W, 0805; Manufacturer: Keystone; Power_W: 500mW; TempCo: ppm/C; U/M: EA; Value: 0; SizeX_mm: 2; SizeY_mm: 1.25; SizeZ_mm: 0.84; Value2: 0.5W; SizeArea_mm2: 2.5; AEC Qualified: N; AEC Category: Q200
R2 R3 R19 = CMP-0078669-1: RES, 10.0 k, 1%, 0.063 W, 0402; Manufacturer: Yageo America; Power_W: 63mW; TempCo: 100 ppm/C; Value_Code: 10k0; Value: 10.0k; EIA_Code: E96; Res_ohm: 10k; SizeX_mm: 1; SizeY_mm: 0.5; SizeZ_mm: 0.6; Value2: 0.063W; AEC Qualified: N; AEC Category: Q200; Green_Lifecycle: Active; Green_REACh: Passed
R4 R18 R33 = CMP-0026740-1: RES, 4.99 k, 1%, 0.063 W, 0402; Manufacturer: Yageo America; Power_W: 63mW; TempCo: 100 ppm/C; Value_Code: 4k99; Value: 4.99k; EIA_Code: E96; SizeX_mm: 1; SizeY_mm: 0.5; SizeZ_mm: 0.6; Value2: 0.063W; AEC Qualified: N; VDC_V: 50V; AEC Category: Q200; U/M: EA
R5 R6 R8 R23 R24 R26 R27 R29 R31 R32 R34 R38 R47 R61 R62 = CMP-0078669-1: RES, 10.0 k, 1%, 0.063 W, 0402; Manufacturer: Yageo America; Power_W: 63mW; Green_Lifecycle: Active; TempCo: 100 ppm/C; Value_Code: 10k0; Green_REACh: Passed; Value: 10.0k; EIA_Code: E96; Res_ohm: 10k; SizeX_mm: 1; SizeY_mm: 0.5; SizeZ_mm: 0.6; Value2: 0.063W; AEC Qualified: N; AEC Category: Q200
R7 = CMP-0026071-3: RES, 1.00 k, 1%, 0.063 W, AEC-Q200 Grade 0, 0402; Manufacturer: Vishay-Dale; Power_W: 63mW; TempCo: 100 ppm/C; Value_Code: 1k00; Value: 1.00k; EIA_Code: E96; Res_ohm: 1k; SizeX_mm: 1; SizeY_mm: 0.5; SizeZ_mm: 0.6; Value2: 0.063W; AEC Qualified: Y; VDC_V: 50V; AEC Category: Q200; AEC Grade: 0
R9 R25 R45 = CMP-0026745-1: RES, 100 k, 1%, 0.063 W, 0402; Manufacturer: Samsung Electro-Mechanics; Power_W: 63mW; TempCo: 100 ppm/C; U/M: EA; Value: 100k; EIA_Code: E96; SizeX_mm: 1; SizeY_mm: 0.5; SizeZ_mm: 0.6; Value2: 0.063W; AEC Qualified: N; VDC_V: 80V; AEC Category: Q200
R10 R14 = CMP-0018748-3: RES, 0, 5%, 0.25 W, AEC-Q200 Grade 0, 1206; Manufacturer: Panasonic; Power_W: 250mW; TempCo: 600 ppm/C; Value_Code: 0000; Value: 0; EIA_Code: E24; SizeX_mm: 3.2; SizeY_mm: 1.6; SizeZ_mm: 1.35; Value2: 0.25W; SizeArea_mm2: 5.12; AEC Qualified: Y; VDC_V: 200V; AEC Category: Q200; SizeAreaWB_mm2: 10.92
R11 R12 = CMP-0023213-5: RES, 60.4, 1%, 0.1 W, 0603; Manufacturer: Yageo; Power_W: 100mW; TempCo: 100 ppm/C; Value_Code: 60R4; Value: 60.4; EIA_Code: E96; SizeX_mm: 1.6; SizeY_mm: 0.8; SizeZ_mm: 1; Value2: 0.1W; SizeArea_mm2: 1.28; AEC Qualified: N; VDC_V: 75V; AEC Category: Q200; SizeAreaWB_mm2: 4.68
R13 R35 = CMP-0026695-1: RES, 3.30 k, 1%, 0.1 W, AEC-Q200 Grade 0, 0402; Manufacturer: Panasonic; Power_W: 100mW; TempCo: 100 ppm/C; Value_Code: 3k30; U/M: EA; Value: 3.30k; Res_ohm: 3.3k; SizeX_mm: 1; SizeY_mm: 0.5; SizeZ_mm: 0.6; Value2: 0.1W; AEC Qualified: Y; VDC_V: 50V; AEC Grade: 0; AEC Category: Q200
R15 = CMP-0026660-1: RES, 1.00 M, 1%, 0.1 W, 0402; Manufacturer: Panasonic; Power_W: 100mW; TempCo: 100 ppm/C; Value_Code: 1M00; U/M: EA; Value: 1.00Meg; EIA_Code: E96; Res_ohm: 1M; SizeX_mm: 1; SizeY_mm: 0.5; SizeZ_mm: 0.6; Value2: 0.1W; VDC_V: 50V; AEC Category: Q200
R16 R58 = CMP-0026298-2: RES, 33.2 k, 1%, 0.063 W, AEC-Q200 Grade 0, 0402; Manufacturer: Vishay-Dale; Power_W: 63mW; TempCo: 100 ppm/C; Value_Code: 33k2; Value: 33.2k; EIA_Code: E96; SizeX_mm: 1; SizeY_mm: 0.5; SizeZ_mm: 0.6; Value2: 0.063W; AEC Qualified: Y; VDC_V: 50V; AEC Category: Q200; AEC Grade: 0
R17 R20 R21 R36 R39-R42 R44 R46 R48-R55 R57 R59 R60 = CMP-0027004-2: RES, 0, 5%, 0.063 W, 0402; Manufacturer: Yageo America; Power_W: 63mW; TempCo: 200 ppm/C; Value_Code: 0000; U/M: EA; Value: 0; EIA_Code: E24; SizeX_mm: 1; SizeY_mm: 0.5; SizeZ_mm: 0.6; Value2: 0.063W; VDC_V: 50V; AEC Category: Q200
R22 R28 = CMP-0026725-1: RES, 1.00 k, 1%, 0.0625 W, 0402; Manufacturer: Yageo America; Power_W: 62.5mW; TempCo: 100 ppm/C; Value_Code: 1k00; Value: 1.00k; EIA_Code: E96; Res_ohm: 1k; SizeX_mm: 1; SizeY_mm: 0.5; SizeZ_mm: 0.6; AEC Qualified: N; VDC_V: 50V; AEC Category: Q200; U/M: EA
R30 = CMP-0026469-2: RES, 5.90 k, 1%, 0.063 W, AEC-Q200 Grade 0, 0402; Manufacturer: Vishay-Dale; Power_W: 63mW; TempCo: 100 ppm/C; Value_Code: 5k90; Value: 5.90k; EIA_Code: E96; Res_ohm: 5.9k; SizeX_mm: 1; SizeY_mm: 0.5; SizeZ_mm: 0.6; Value2: 0.063W; AEC Qualified: Y; VDC_V: 50V; AEC Category: Q200; AEC Grade: 0
R37 R43 = CMP-0026088-3: RES, 1.50 k, 1%, 0.063 W, AEC-Q200 Grade 0, 0402; Manufacturer: Vishay-Dale; Power_W: 63mW; TempCo: 100 ppm/C; Value_Code: 1k50; Value: 1.50k; EIA_Code: E96; Res_ohm: 1.5k; SizeX_mm: 1; SizeY_mm: 0.5; SizeZ_mm: 0.6; Value2: 0.063W; AEC Qualified: Y; VDC_V: 50V; AEC Category: Q200; AEC Grade: 0
R56 = CMP-0026050-3: RES, 17.4 k, 1%, 0.063 W, AEC-Q200 Grade 0, 0402; Manufacturer: Vishay-Dale; Power_W: 63mW; TempCo: 100 ppm/C; Value_Code: 17k4; Value: 17.4k; EIA_Code: E96; SizeX_mm: 1; SizeY_mm: 0.5; SizeZ_mm: 0.6; Value2: 0.063W; AEC Qualified: Y; VDC_V: 50V; AEC Category: Q200; AEC Grade: 0
S1 S2 = CMP-0002150-2: SWITCH TACTILE SPST-NO 0.05A 12V; Manufacturer: Omron Electronic Components; CurrentRating_mA: 50A; PositionCount: 1; SwitchFunction: Off-Mom
TP1 = CMP-0055147-1: Test Point, Multipurpose, Red, TH; Manufacturer: Keystone; CNHeader: FALSE; Green_Lifecycle: Active; Green_REACh: Passed; ContactFinish: Silver; CT: TRUE
TP2 = CMP-0055148-1: Test Point, Multipurpose, Black, TH; Manufacturer: Keystone; CNHeader: FALSE; Green_Lifecycle: Active; Green_REACh: Passed; ContactFinish: Silver; CT: TRUE
TP3-TP5 = CMP-0003825-1: 1mm Test Point, SMT; Manufacturer: Any
U1 = CMP-0079160-1: Fault Protected Local Interconnect Network (LIN) Transceiver with Dominant State Timeout, D0008A (SOIC-8); Alternate PartNumber: TLIN2029DRQ1; Alternate Manufacturer: Texas Instruments; SizeAreaWB_mm2: 56.58; SizeZ_mm: 1.75; SizeX_mm: 4.9; SizeY_mm: 6.2; SizeArea_mm2: 30.38; CompType: IC; AEC Qualified: Y; AEC Category: Q200
U2 = CMP-0065224-7: CAN-FD Controller with Integrated Transceiver, RGY0020A (VQFN-20); Alternate PartNumber: TCAN4550RGYQ1; Manufacturer: Texas Instruments; SizeZ_mm: 1.0; SizeX_mm: 3.5; SizeY_mm: 4.5; SizeArea_mm2: 15.75; CompType: IC; SizeAreaWB_mm2: 24.75; AEC Category: Q200; AEC Qualified: Y; Rating: Automotive
U3 = CMP-0073734-2: Dual-Channel Antenna LDO With Current Sense, PWP0016J (TSSOP-16); Manufacturer: Texas Instruments; SizeX_mm: 6.4; SizeY_mm: 5.0; CompType: IC; SizeZ_mm: 1.2; SizeArea_mm2: 32.0; SizeAreaWB_mm2: 58.8; U/M: EA; Green_Lifecycle: Active; Green_REACh: Passed
U4 = CMP-0051651-2: Low Power, 1.8/2.5/3.3-V Input, 3.3-V CMOS Output, Single Inverter Gate, DCK0005A, LARGE T&R; Manufacturer: Texas Instruments; Voltage(Nom)(V): 1.8,2.5,3.3; Technology Family: AUP1T; ICC @ Nom Voltage(Max)(mA): 0.0009; VCC(Max)(V): 3.6; 3-State Output: No; Sub-Family: Single Supply Translator; Rating: Catalog; Bits(#): 1; Output Drive (IOL/IOH)(Max)(mA): 4/-4; tpd @ Nom Voltage(Max)(ns): 9.8,8.5,7.8; Logic: True; F @ Nom Voltage(Max)(Mhz): 190; VCC(Min)(V): 0.8; AEC Category: Q200; AEC Qualified: N; CompType: IC; SizeAreaWB_mm2: 9.3; SizeArea_mm2: 4.2; SizeX_mm: 2.1; SizeY_mm: 2.0; SizeZ_mm: 1.1
Y1 = CMP-0085289-1: Crystal, 40 MHz, 10 ppm, 8 pF, AEC-Q200 Grade 0, SMD; Manufacturer: NDK; TaMin_C: -40°C; Frequency Stability: 25 ppm; TaMax_C: 125°C; AEC Category: Q200; AEC Grade: 0; AEC Qualified: Y; Frequency Tolerance: 10 ppm; Load Capacitance: 8 pF

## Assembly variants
001: not fitted FID1 FID2 FID3 L2 R40 R41 R57 R58 R59 R61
